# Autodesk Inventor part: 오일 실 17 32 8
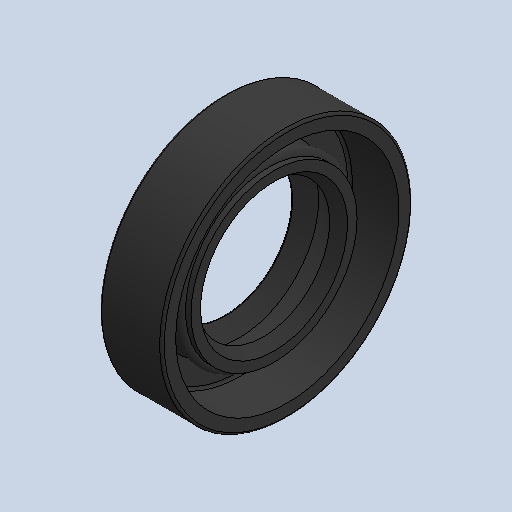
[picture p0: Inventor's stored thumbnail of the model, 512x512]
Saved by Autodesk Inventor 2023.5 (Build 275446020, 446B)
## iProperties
Created: 2026-07
Part Number: 오일 실 17 32 8
Material: 고무
Description: 오일-실
Document SubType Name: Modeling
Designer: mirae
Density: 0.93 g/cm^3
Appearance: 기본값
Author: jhkim
Revision Number: 1
Sending System: Autodesk Inventor 2027
Preprocessor: ST-DEVELOPER v20.1
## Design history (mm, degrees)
node "오일 실 17 32 81"
node "솔리드1"
body "Solid1"
